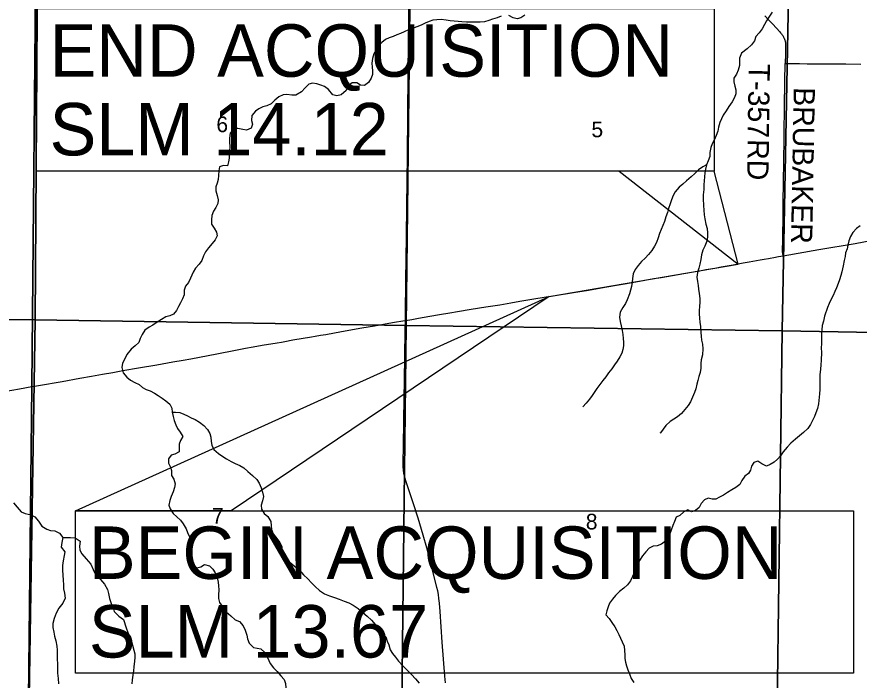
# Model space of a CAD drawing. Extents: x -8.8 to 41.4, y 0 to 34.6.
# Drawn here: x -5.453 to -3.204, y 16.599 to 18.37 of the extents above; entities that cross this region are included whole.
import ezdxf

# ---------------------------------------------------------------- set-up
doc = ezdxf.new("R2010")
doc.units = 0
for name, color, linetype in [('Default', 7, 'Continuous'), ('GM_X_Corporation', 7, 'Continuous'), ('GM_X_County_Road', 7, 'Continuous'), ('GM_X_Minor_River', 7, 'Continuous'), ('GM_X_Section_Text', 7, 'Continuous'), ('GM_X_State_Route', 7, 'Continuous'), ('GM_X_Township_Road', 7, 'Continuous'), ('GM_X_Township_Text', 7, 'Continuous'), ('SH_Border', 7, 'Continuous'), ('SH_Data', 7, 'Continuous')]:
    doc.layers.add(name, color=color, linetype=linetype)

msp = doc.modelspace()

# ---------------------------------------------------------------- linework, layer by layer
at = {"layer": 'GM_X_Corporation'}
for points in [[(-8.6743, 18.6925), (-8.6743, 14.1), (-5.4442, 14.1), (-5.4432, 14.2265), (-5.4429, 14.2618), (-5.4404, 14.5882), (-5.4368, 15.0446), (-5.435, 15.3164), (-5.4282, 16.3507), (-5.4212, 16.5483), (-5.4129, 17.3836), (-5.4008, 18.6369)], [(-5.4008, 18.6369), (-5.4129, 17.3836), (-5.4212, 16.5483), (-5.4282, 16.3507), (-5.435, 15.3164), (-5.4368, 15.0446), (-5.4404, 14.5882), (-5.4429, 14.2618), (-5.4432, 14.2265), (-5.4442, 14.1), (-1.8743, 14.1), (-1.8743, 18.5906)]]:
    msp.add_lwpolyline(points, dxfattribs=at)
for points in [[(-6.4037, 18.6579), (-5.3971, 18.6428), (-5.4036, 17.5614), (-6.4092, 17.5696)], [(-5.3971, 18.6428), (-4.4269, 18.629), (-4.4012, 18.628), (-4.4134, 17.5464), (-5.4036, 17.5614)], [(-4.4012, 18.628), (-3.4272, 18.6145), (-3.3893, 18.614), (-3.4102, 17.5315), (-4.4134, 17.5464)], [(-3.3893, 18.614), (-2.4092, 18.5999), (-2.4162, 17.5144), (-3.4102, 17.5315)], [(-5.4036, 17.5614), (-5.4203, 16.5519), (-6.4339, 16.586), (-6.4092, 17.5696)], [(-4.4134, 17.5464), (-4.4254, 16.539), (-5.4203, 16.5519), (-5.4036, 17.5614)], [(-3.4102, 17.5315), (-3.4233, 16.5283), (-4.4254, 16.539), (-4.4134, 17.5464)], [(-2.4162, 17.5144), (-2.421, 16.5107), (-3.4233, 16.5283), (-3.4102, 17.5315)]]:
    msp.add_lwpolyline(points, close=True, dxfattribs=at)
at = {"layer": 'GM_X_County_Road'}
for points in [[(-4.4156, 17.5596), (-4.4156, 17.5608), (-4.4157, 17.577), (-4.4143, 17.6658), (-4.4129, 17.7838), (-4.4119, 17.8646), (-4.4102, 17.9994), (-4.409, 18.1094), (-4.4082, 18.2175), (-4.4071, 18.3032), (-4.4063, 18.3609), (-4.4057, 18.4379), (-4.4051, 18.51), (-4.4044, 18.5765), (-4.4046, 18.5896), (-4.405, 18.5964), (-4.4057, 18.6014), (-4.4066, 18.6057), (-4.4077, 18.6094), (-4.4095, 18.6141), (-4.4119, 18.6189), (-4.4135, 18.6221), (-4.4151, 18.6247), (-4.4171, 18.6274)], [(-4.3088, 16.5919), (-4.3103, 16.6099), (-4.317, 16.7004), (-4.3228, 16.7822), (-4.3246, 16.8045), (-4.3261, 16.8175), (-4.3276, 16.828), (-4.3293, 16.8372), (-4.3314, 16.8469), (-4.3501, 16.9223), (-4.3581, 16.9528), (-4.3679, 16.9864), (-4.3811, 17.0315), (-4.3939, 17.0701), (-4.4072, 17.1096), (-4.4134, 17.1284), (-4.4169, 17.1403), (-4.4193, 17.1505), (-4.4208, 17.1603), (-4.4215, 17.1689), (-4.4217, 17.1782), (-4.4208, 17.226), (-4.4191, 17.3527), (-4.4183, 17.3993), (-4.4162, 17.531), (-4.4156, 17.5596)]]:
    msp.add_lwpolyline(points, dxfattribs=at)
at = {"layer": 'GM_X_Minor_River'}
for points in [[(-4.1595, 18.372), (-4.1709, 18.368), (-4.1828, 18.3637), (-4.1927, 18.3601), (-4.2042, 18.3572), (-4.2159, 18.3559), (-4.2281, 18.3562), (-4.2402, 18.3556), (-4.2527, 18.3559), (-4.2645, 18.3568), (-4.2747, 18.3578), (-4.2853, 18.3584), (-4.2963, 18.3597), (-4.3069, 18.3614), (-4.3202, 18.3632), (-4.3315, 18.3626), (-4.3422, 18.3613), (-4.3521, 18.3577), (-4.3625, 18.353), (-4.3736, 18.3483), (-4.3846, 18.3439), (-4.3965, 18.3392), (-4.4076, 18.3352), (-4.4187, 18.3301)], [(-4.0968, 18.3746), (-4.1072, 18.3676), (-4.1171, 18.3651), (-4.1281, 18.3676), (-4.1397, 18.3739)], [(-3.4368, 18.3828), (-3.4454, 18.3697), (-3.4517, 18.3599), (-3.4568, 18.3498), (-3.4631, 18.3378), (-3.4716, 18.3277), (-3.4798, 18.318), (-3.4841, 18.3063), (-3.4916, 18.2951), (-3.5028, 18.2847), (-3.5181, 18.2736), (-3.5233, 18.26), (-3.5235, 18.2502), (-3.5241, 18.2399), (-3.5269, 18.2279), (-3.5321, 18.2169), (-3.5391, 18.2065), (-3.5389, 18.197), (-3.5365, 18.1852), (-3.5332, 18.1753), (-3.5338, 18.1647), (-3.5374, 18.1549), (-3.5437, 18.1432), (-3.5523, 18.1309), (-3.5597, 18.1193), (-3.5671, 18.108), (-3.5758, 18.0877), (-3.5795, 18.0756), (-3.5819, 18.0647), (-3.5856, 18.0538), (-3.5907, 18.0429), (-3.597, 18.0312), (-3.6002, 18.021), (-3.6027, 18.0082), (-3.6033, 17.9972), (-3.6077, 17.9859), (-3.612, 17.975), (-3.6149, 17.9637), (-3.6162, 17.9535), (-3.6172, 17.9432), (-3.6181, 17.9323), (-3.6187, 17.9213), (-3.6193, 17.9095), (-3.6204, 17.8948), (-3.6205, 17.8845), (-3.6194, 17.8663), (-3.6188, 17.8542), (-3.6179, 17.8413), (-3.6162, 17.8306), (-3.6134, 17.8165), (-3.6102, 17.8047), (-3.6089, 17.7937), (-3.6092, 17.7816), (-3.6112, 17.771), (-3.6164, 17.7582), (-3.6219, 17.7469), (-3.6248, 17.7348), (-3.6273, 17.7224), (-3.6298, 17.7095), (-3.6319, 17.6993), (-3.6355, 17.688), (-3.6377, 17.6755), (-3.636, 17.6638), (-3.6343, 17.6527), (-3.6333, 17.6432), (-3.6317, 17.6311), (-3.63, 17.6185), (-3.6298, 17.6075), (-3.6304, 17.5977)], [(-4.4187, 18.3301), (-4.429, 18.3254), (-4.4385, 18.3218), (-4.4485, 18.3182), (-4.4592, 18.3142), (-4.4687, 18.3094), (-4.4788, 18.3017), (-4.4873, 18.2916), (-4.4935, 18.2818), (-4.4998, 18.2713), (-4.5034, 18.2589), (-4.5052, 18.2464), (-4.5046, 18.2358), (-4.5037, 18.2259), (-4.5035, 18.216), (-4.5071, 18.2063), (-4.5137, 18.195), (-4.5245, 18.1869), (-4.5351, 18.1882), (-4.5456, 18.1944), (-4.5578, 18.1939), (-4.5674, 18.1865), (-4.5737, 18.1734), (-4.5872, 18.1622), (-4.599, 18.159), (-4.6096, 18.1623), (-4.6207, 18.1765), (-4.6312, 18.1839), (-4.641, 18.1882), (-4.6519, 18.1915), (-4.6633, 18.1932), (-4.6732, 18.1904), (-4.6829, 18.1803), (-4.6929, 18.1699), (-4.7082, 18.1614), (-4.7189, 18.1609), (-4.7317, 18.163), (-4.742, 18.1617), (-4.7531, 18.157), (-4.7639, 18.1481), (-4.7735, 18.1384), (-4.785, 18.1329), (-4.7957, 18.1297), (-4.8064, 18.125), (-4.816, 18.1183), (-4.8257, 18.1071), (-4.8267, 18.0931), (-4.8235, 18.0836), (-4.8275, 18.073), (-4.8393, 18.0679), (-4.8492, 18.0696), (-4.8624, 18.0725), (-4.8723, 18.0719), (-4.8831, 18.0596), (-4.8853, 18.0464), (-4.8851, 18.0362), (-4.8842, 18.0236), (-4.8848, 18.0123), (-4.8859, 17.9933), (-4.888, 17.9835), (-4.8904, 17.9726), (-4.901, 17.9735), (-4.9114, 17.9695), (-4.9138, 17.9593), (-4.9141, 17.9468), (-4.9154, 17.9359), (-4.9182, 17.9261), (-4.9214, 17.9163), (-4.9213, 17.9053), (-4.9177, 17.8934), (-4.9149, 17.882), (-4.9162, 17.8718), (-4.9217, 17.8613), (-4.928, 17.8512), (-4.932, 17.8395), (-4.9333, 17.8281), (-4.9335, 17.8171), (-4.9261, 17.8064), (-4.9195, 17.7957), (-4.9178, 17.7854), (-4.9233, 17.7749), (-4.9311, 17.7652), (-4.9411, 17.7532), (-4.9493, 17.7424), (-4.9548, 17.7318), (-4.9588, 17.7198), (-4.9658, 17.7097), (-4.9755, 17.6992), (-4.9818, 17.6887), (-4.9893, 17.6726), (-4.9944, 17.6609), (-5.0022, 17.6508), (-5.0058, 17.6403), (-5.0064, 17.6278), (-5.0108, 17.6172), (-5.0163, 17.6067), (-5.021, 17.5966), (-5.0266, 17.5861), (-5.0347, 17.5764), (-5.0443, 17.5716), (-5.0549, 17.5688)], [(-3.612, 17.975), (-3.622, 17.9695), (-3.6332, 17.9614), (-3.6432, 17.9521), (-3.6529, 17.9431), (-3.6648, 17.932), (-3.6748, 17.9238), (-3.6845, 17.9153), (-3.6953, 17.9026), (-3.7008, 17.8929), (-3.7048, 17.8819), (-3.7084, 17.871), (-3.7128, 17.8586), (-3.7161, 17.848), (-3.7201, 17.836), (-3.7241, 17.8235), (-3.7372, 17.7919), (-3.7412, 17.7799), (-3.7456, 17.7678), (-3.7507, 17.7577), (-3.7578, 17.7468), (-3.7667, 17.7356), (-3.7756, 17.7259), (-3.7856, 17.717), (-3.7946, 17.7065), (-3.8024, 17.6957), (-3.8071, 17.6844), (-3.8092, 17.6719), (-3.8106, 17.6617), (-3.8123, 17.65), (-3.8144, 17.6402), (-3.8176, 17.6304), (-3.824, 17.6149), (-3.8283, 17.6048), (-3.835, 17.5939), (-3.842, 17.5815), (-3.8442, 17.5687), (-3.8425, 17.5565), (-3.8393, 17.5455), (-3.8369, 17.5325), (-3.8348, 17.5219), (-3.8338, 17.5116), (-3.8333, 17.5014), (-3.833, 17.4919), (-3.8347, 17.482), (-3.8376, 17.4722), (-3.8431, 17.4621), (-3.8501, 17.4512), (-3.8571, 17.4415), (-3.8645, 17.4303), (-3.8731, 17.4198), (-3.8809, 17.4093), (-3.8882, 17.3996), (-3.8964, 17.3888), (-3.9042, 17.3779), (-3.9171, 17.3592), (-3.9245, 17.3491), (-3.933, 17.3387), (-3.9415, 17.329)], [(-3.2014, 17.8123), (-3.2115, 17.8049), (-3.2211, 17.794), (-3.227, 17.7835), (-3.2322, 17.7723), (-3.2346, 17.7609), (-3.2367, 17.7507), (-3.2403, 17.7402), (-3.242, 17.7303), (-3.2441, 17.7194), (-3.2471, 17.705), (-3.2504, 17.6895), (-3.2528, 17.6794), (-3.2565, 17.668), (-3.2604, 17.6579), (-3.2644, 17.647), (-3.2692, 17.6372), (-3.2739, 17.6263), (-3.2787, 17.6161), (-3.2842, 17.6045), (-3.2886, 17.5939), (-3.2966, 17.5713), (-3.2999, 17.5578), (-3.3027, 17.5461), (-3.3041, 17.5343), (-3.3047, 17.5214), (-3.3049, 17.5097), (-3.3047, 17.4983), (-3.3054, 17.4858), (-3.3052, 17.4748), (-3.3056, 17.4528), (-3.3062, 17.4418), (-3.3072, 17.4286), (-3.3089, 17.4154), (-3.3095, 17.4025), (-3.3094, 17.3922), (-3.3093, 17.3748), (-3.3099, 17.3638), (-3.313, 17.3373), (-3.3155, 17.3245), (-3.3199, 17.3132), (-3.3239, 17.303), (-3.3286, 17.2925), (-3.3342, 17.2816), (-3.3416, 17.2707), (-3.3528, 17.26), (-3.3639, 17.2514), (-3.3743, 17.2429), (-3.3863, 17.2321)], [(-3.6304, 17.5977), (-3.6317, 17.5856), (-3.6315, 17.5761), (-3.6306, 17.5662), (-3.6293, 17.5544), (-3.6279, 17.5442), (-3.6267, 17.5275), (-3.6261, 17.518), (-3.6248, 17.5066), (-3.6228, 17.4959), (-3.6215, 17.4841), (-3.6229, 17.4679), (-3.6258, 17.4543), (-3.6267, 17.4444), (-3.627, 17.4323), (-3.6287, 17.4206), (-3.6323, 17.41), (-3.6348, 17.3994), (-3.6376, 17.3893), (-3.6405, 17.3768), (-3.6441, 17.367), (-3.6493, 17.355), (-3.6548, 17.3426), (-3.6611, 17.3321), (-3.6692, 17.322), (-3.6789, 17.3108), (-3.6889, 17.3022), (-3.6993, 17.2956), (-3.7089, 17.2894), (-3.7201, 17.2789), (-3.7279, 17.2692), (-3.7345, 17.2595), (-3.736, 17.2584)], [(-5.0549, 17.5688), (-5.0665, 17.5622), (-5.078, 17.5548), (-5.0899, 17.547), (-5.0998, 17.5419), (-5.111, 17.5338), (-5.118, 17.5218), (-5.1232, 17.5116), (-5.1275, 17.5011), (-5.1372, 17.4922), (-5.1476, 17.4829), (-5.1589, 17.4683), (-5.1648, 17.457), (-5.1703, 17.4454), (-5.1724, 17.4337), (-5.1685, 17.4196), (-5.1592, 17.408), (-5.1491, 17.3999), (-5.1379, 17.3936), (-5.1266, 17.3885), (-5.1169, 17.3803), (-5.1071, 17.3748), (-5.0965, 17.3712), (-5.0856, 17.3657), (-5.0759, 17.3591), (-5.0646, 17.3521), (-5.0549, 17.3451), (-5.0444, 17.3358), (-5.0386, 17.3254), (-5.0384, 17.3148), (-5.0359, 17.303), (-5.0327, 17.2923), (-5.0284, 17.2813), (-5.0236, 17.2713), (-5.0166, 17.2609), (-5.01, 17.2494), (-5.0159, 17.2393), (-5.0198, 17.2292), (-5.0193, 17.2193), (-5.0191, 17.209), (-5.0306, 17.2024), (-5.0409, 17.2), (-5.0483, 17.1902), (-5.0481, 17.1785), (-5.0422, 17.1681), (-5.0401, 17.1586), (-5.0396, 17.1457), (-5.0333, 17.1358), (-5.0298, 17.1236), (-5.0318, 17.1134), (-5.0358, 17.1021), (-5.0406, 17.0896), (-5.0446, 17.0787), (-5.0467, 17.0662), (-5.0431, 17.0567), (-5.0354, 17.0437), (-5.0257, 17.0355), (-5.0156, 17.0266), (-5.0086, 17.0162), (-5.0012, 17.0028), (-4.9969, 16.9933), (-4.9918, 16.9818), (-4.9924, 16.9697), (-4.9971, 16.958), (-4.9989, 16.9471), (-4.9983, 16.9376), (-4.9985, 16.9277), (-4.991, 16.9181), (-4.9836, 16.9085), (-4.972, 16.8992), (-4.9617, 16.902), (-4.9518, 16.9083), (-4.9389, 16.9042), (-4.9292, 16.8953), (-4.923, 16.8854), (-4.9179, 16.8724), (-4.9155, 16.8606), (-4.9145, 16.8511), (-4.9139, 16.8405), (-4.9146, 16.8268), (-4.9147, 16.817), (-4.9115, 16.8067), (-4.903, 16.7936), (-4.8941, 16.7817), (-4.8818, 16.7705), (-4.8703, 16.7604), (-4.8586, 16.7556), (-4.8482, 16.7444), (-4.8431, 16.7326), (-4.8391, 16.7196), (-4.837, 16.7097), (-4.8323, 16.6983), (-4.8211, 16.6867), (-4.8113, 16.6846), (-4.8011, 16.6825), (-4.7907, 16.6729), (-4.7833, 16.6598), (-4.7768, 16.6438), (-4.7675, 16.6319), (-4.7578, 16.6222), (-4.7482, 16.6107)], [(-5.0384, 17.3148), (-5.0289, 17.3146), (-5.0175, 17.314), (-5.0074, 17.3097), (-4.9976, 17.3053), (-4.987, 17.2998), (-4.9769, 17.2947), (-4.9653, 17.2884), (-4.9537, 17.2795), (-4.9436, 17.2683), (-4.9377, 17.2576), (-4.9353, 17.2481), (-4.934, 17.2363), (-4.9326, 17.2264), (-4.9268, 17.2153), (-4.9144, 17.2045), (-4.9028, 17.1967), (-4.8927, 17.1904), (-4.8807, 17.183), (-4.8698, 17.1775), (-4.8574, 17.1723), (-4.8472, 17.1657), (-4.8364, 17.156), (-4.8233, 17.1455), (-4.8125, 17.1351), (-4.8055, 17.1255), (-4.8004, 17.1125), (-4.7968, 17.1007), (-4.794, 17.0896), (-4.7969, 17.0775), (-4.8005, 17.0666), (-4.7995, 17.056), (-4.7926, 17.0441), (-4.7825, 17.0363), (-4.7744, 17.0229), (-4.7738, 17.0111), (-4.7732, 17.0016), (-4.7681, 16.9894), (-4.7585, 16.9771), (-4.7507, 16.9663), (-4.7452, 16.956), (-4.7458, 16.9462), (-4.7464, 16.9344), (-4.7364, 16.9221), (-4.7251, 16.9151), (-4.7117, 16.9031), (-4.699, 16.8933), (-4.6874, 16.8806), (-4.6762, 16.8698), (-4.6658, 16.8594), (-4.6561, 16.8493), (-4.6446, 16.8381), (-4.6315, 16.8292), (-4.6183, 16.824), (-4.6051, 16.8199), (-4.5923, 16.8155), (-4.5787, 16.8104), (-4.5663, 16.8056), (-4.5546, 16.7997), (-4.5415, 16.7903), (-4.5288, 16.7802), (-4.5176, 16.7702), (-4.506, 16.759), (-4.4952, 16.7466), (-4.4863, 16.7366), (-4.4763, 16.725), (-4.4681, 16.7147), (-4.4638, 16.7036), (-4.4598, 16.6933), (-4.4562, 16.6803), (-4.45, 16.67), (-4.4422, 16.6603), (-4.434, 16.6496), (-4.4221, 16.6376), (-4.4102, 16.6249), (-4.3994, 16.6144), (-4.389, 16.6025), (-4.379, 16.5909)], [(-3.3863, 17.2321), (-3.3964, 17.221), (-3.4068, 17.2086), (-3.4146, 17.1985), (-3.422, 17.1888), (-3.4316, 17.181), (-3.4416, 17.1748), (-3.4515, 17.1704), (-3.4643, 17.1771), (-3.4752, 17.1841), (-3.4855, 17.1802), (-3.4914, 17.1704), (-3.4946, 17.1602), (-3.4993, 17.1505), (-3.5093, 17.1442), (-3.5175, 17.1318), (-3.5226, 17.1217), (-3.5334, 17.1139), (-3.5445, 17.1077), (-3.556, 17.1003), (-3.566, 17.0933), (-3.5768, 17.0878), (-3.5867, 17.0827), (-3.597, 17.0825), (-3.6072, 17.0854), (-3.6171, 17.0802), (-3.6257, 17.0705), (-3.6315, 17.0604), (-3.6412, 17.0522), (-3.6522, 17.0483), (-3.662, 17.0538), (-3.672, 17.0486), (-3.6828, 17.0386), (-3.6924, 17.0339), (-3.6971, 17.023), (-3.7015, 17.012), (-3.7063, 17), (-3.7099, 16.9902), (-3.7142, 16.9804), (-3.7212, 16.9699), (-3.7316, 16.9622), (-3.7431, 16.9578), (-3.7545, 16.9565), (-3.7648, 16.9514), (-3.7737, 16.9417), (-3.7827, 16.9309), (-3.7909, 16.9185), (-3.7964, 16.9073), (-3.8095, 16.8757), (-3.815, 16.8644), (-3.8228, 16.8535), (-3.8328, 16.8446), (-3.844, 16.8354), (-3.8548, 16.8249), (-3.8626, 16.8152), (-3.8711, 16.8051), (-3.8743, 16.795), (-3.8776, 16.784), (-3.8808, 16.7739), (-3.8715, 16.7634), (-3.8641, 16.7527), (-3.8567, 16.7412), (-3.8508, 16.7316), (-3.8457, 16.7213), (-3.8414, 16.7109), (-3.8366, 16.7014), (-3.8315, 16.6899), (-3.8306, 16.6785), (-3.83, 16.6667), (-3.8298, 16.6573), (-3.8281, 16.647), (-3.8256, 16.6371), (-3.822, 16.6268), (-3.8177, 16.6157), (-3.8126, 16.6035), (-3.8056, 16.5931)], [(-5.462, 17.0723), (-5.4517, 17.0611), (-5.441, 17.0483), (-5.4305, 17.0442), (-5.4146, 17.0404), (-5.4045, 17.0356), (-5.3946, 17.0236), (-5.3862, 17.0105), (-5.3731, 17.0022), (-5.363, 16.9986), (-5.3512, 16.9979), (-5.3392, 16.9919), (-5.3301, 16.9796), (-5.3323, 16.9667), (-5.3341, 16.9546), (-5.3249, 16.9415), (-5.3263, 16.9317), (-5.3293, 16.9177), (-5.3312, 16.9049), (-5.3307, 16.8924), (-5.3299, 16.8798), (-5.3287, 16.8665), (-5.3283, 16.8532), (-5.3278, 16.843), (-5.3254, 16.8312), (-5.3238, 16.8179), (-5.3302, 16.8047), (-5.3404, 16.7917), (-5.348, 16.7782), (-5.3533, 16.764), (-5.357, 16.75), (-5.3569, 16.7394), (-5.3542, 16.7268), (-5.3522, 16.7165), (-5.3483, 16.7039), (-5.346, 16.6898), (-5.3447, 16.6796), (-5.3447, 16.6667), (-5.3449, 16.6568), (-5.3445, 16.6412), (-5.3445, 16.6299), (-5.344, 16.6181), (-5.3425, 16.6036), (-5.3417, 16.5892)], [(-5.3301, 16.9796), (-5.3225, 16.9798), (-5.3099, 16.9798), (-5.2967, 16.9791), (-5.2833, 16.9705), (-5.2851, 16.9572), (-5.285, 16.9466), (-5.2792, 16.9362), (-5.2674, 16.923), (-5.2552, 16.9091), (-5.2487, 16.8945), (-5.2433, 16.8826), (-5.2293, 16.8675), (-5.2186, 16.8555), (-5.211, 16.8409), (-5.2078, 16.8306), (-5.2051, 16.8172), (-5.2009, 16.8038), (-5.1955, 16.7927), (-5.1931, 16.782), (-5.1809, 16.7696), (-5.1682, 16.7613), (-5.1612, 16.7384), (-5.1566, 16.7265), (-5.1508, 16.7142), (-5.1469, 16.7028), (-5.1442, 16.6921), (-5.1407, 16.6795), (-5.1379, 16.6692), (-5.1374, 16.6593), (-5.1384, 16.6495), (-5.1403, 16.6343), (-5.1417, 16.6238), (-5.1431, 16.6128), (-5.1449, 16.5996), (-5.1456, 16.589)], [(-4.7482, 16.6107), (-4.7389, 16.6006), (-4.7356, 16.5903), (-4.7343, 16.5785), (-4.7364, 16.5676), (-4.7389, 16.5574), (-4.7315, 16.5459), (-4.7203, 16.5392), (-4.709, 16.5345), (-4.6992, 16.5313), (-4.6906, 16.5205), (-4.6909, 16.5084), (-4.6914, 16.4981), (-4.6916, 16.4883), (-4.6926, 16.4781)]]:
    msp.add_lwpolyline(points, dxfattribs=at)
at = {"layer": 'GM_X_State_Route'}
for points in [[(-5.4117, 17.3832), (-5.3947, 17.3863), (-5.3322, 17.397), (-5.2844, 17.4052), (-5.2538, 17.4106), (-5.2245, 17.4158), (-5.1969, 17.4206), (-5.17, 17.4255), (-5.1278, 17.4327), (-5.0795, 17.4413), (-5.0366, 17.4491), (-5.0085, 17.4539), (-4.9883, 17.4575), (-4.9419, 17.4664), (-4.9187, 17.4707), (-4.8687, 17.4803), (-4.8424, 17.4854), (-4.8217, 17.4892), (-4.7978, 17.4932), (-4.7579, 17.5), (-4.7463, 17.502), (-4.7378, 17.5036), (-4.7163, 17.5074), (-4.6661, 17.5159), (-4.6563, 17.5176), (-4.6422, 17.52), (-4.6282, 17.5224), (-4.586, 17.53), (-4.5321, 17.5396), (-4.4978, 17.5456), (-4.4501, 17.5539), (-4.417, 17.5594), (-4.4156, 17.5596), (-4.398, 17.5624), (-4.3808, 17.5653), (-4.3502, 17.5707), (-4.3245, 17.5751), (-4.2969, 17.5798), (-4.2761, 17.5831), (-4.2399, 17.5893), (-4.2007, 17.5957), (-4.1639, 17.6017), (-4.1339, 17.6066), (-4.11, 17.6108), (-4.0781, 17.616), (-4.0401, 17.6223), (-4.0156, 17.6264), (-3.9665, 17.6342), (-3.9266, 17.6407), (-3.8776, 17.6491), (-3.8519, 17.6535), (-3.8311, 17.6572), (-3.8006, 17.6628), (-3.7528, 17.6713), (-3.7332, 17.6747), (-3.7179, 17.6773), (-3.672, 17.6851), (-3.6463, 17.6895), (-3.6298, 17.6924), (-3.6139, 17.6952), (-3.5894, 17.6994), (-3.5722, 17.7024), (-3.541, 17.708), (-3.5319, 17.7097), (-3.5136, 17.7131), (-3.4977, 17.7161), (-3.4683, 17.7213), (-3.4579, 17.7231), (-3.4463, 17.7253), (-3.4421, 17.7262), (-3.4317, 17.728), (-3.42, 17.7301), (-3.4074, 17.7324), (-3.3118, 17.7487), (-3.2151, 17.7654), (-3.1735, 17.7729)], [(-5.4865, 17.3703), (-5.4461, 17.3772), (-5.4127, 17.3831), (-5.4117, 17.3832)]]:
    msp.add_lwpolyline(points, dxfattribs=at)
at = {"layer": 'GM_X_Township_Road'}
for points in [[(-3.4565, 18.3726), (-3.445, 18.3612), (-3.4399, 18.3559), (-3.4348, 18.3505), (-3.4163, 18.3304), (-3.4143, 18.328), (-3.4119, 18.3252), (-3.4103, 18.3231), (-3.4092, 18.3215), (-3.4083, 18.32), (-3.4072, 18.3183), (-3.406, 18.3163), (-3.4052, 18.3146), (-3.4045, 18.313), (-3.4035, 18.3106), (-3.4026, 18.3081), (-3.4021, 18.3058), (-3.4017, 18.3038), (-3.4013, 18.3019), (-3.4011, 18.3004), (-3.4009, 18.2984), (-3.4008, 18.2949), (-3.4009, 18.2891), (-3.4011, 18.2736), (-3.4013, 18.2656), (-3.4016, 18.2524), (-3.4017, 18.2454)], [(-3.4074, 17.7324), (-3.4083, 17.7376), (-3.4084, 17.7391), (-3.4085, 17.7415), (-3.4085, 17.7447), (-3.4085, 17.7535), (-3.4084, 17.7665), (-3.4081, 17.7826), (-3.4077, 17.8031), (-3.4074, 17.8179), (-3.4072, 17.8408), (-3.407, 17.8577), (-3.4067, 17.88), (-3.4062, 17.9235), (-3.4059, 17.9493), (-3.4057, 17.9631), (-3.4055, 17.9787), (-3.4052, 18.0014), (-3.4049, 18.0282), (-3.4046, 18.046), (-3.4043, 18.0703), (-3.4041, 18.0891), (-3.404, 18.0999), (-3.4039, 18.1118), (-3.4035, 18.1346), (-3.4032, 18.1562), (-3.403, 18.1705), (-3.4026, 18.2041), (-3.4023, 18.2173), (-3.4021, 18.2266), (-3.4018, 18.2334), (-3.4017, 18.2454)], [(-3.4017, 18.2454), (-3.3949, 18.2454), (-3.3844, 18.2454), (-3.3633, 18.2453), (-3.3427, 18.2452), (-3.32, 18.2451), (-3.2959, 18.245), (-3.2713, 18.2448), (-3.2402, 18.2446), (-3.1998, 18.2443)]]:
    msp.add_lwpolyline(points, dxfattribs=at)
at = {"layer": 'SH_Border'}
msp.add_line((-4.0317, 17.6231), (-3.5271, 17.7103), dxfattribs=at)
at = {"layer": 'SH_Data'}
for points in [[(-5.4009, 18.3923), (-3.5915, 18.3923), (-3.5915, 17.9584), (-5.4009, 17.9584)], [(-3.8448, 17.9586), (-3.5271, 17.7103), (-3.5915, 17.9584)], [(-5.2961, 17.0515), (-4.0317, 17.6231), (-4.8804, 17.0512)], [(-5.2961, 17.0515), (-3.2195, 17.0515), (-3.2195, 16.6176), (-5.2961, 16.6176)]]:
    msp.add_lwpolyline(points, close=True, dxfattribs=at)

# ---------------------------------------------------------------- texts
at = {"layer": 'Default'}
for s, p in [('END ACQUISITION', (-5.3654, 18.2103)), ('SLM 14.12', (-5.3654, 18.0003)), ('BEGIN ACQUISITION', (-5.2605, 16.8695)), ('SLM 13.67', (-5.2605, 16.6595))]:
    msp.add_text(s, height=0.14, dxfattribs=at).set_placement(p)
at = {"layer": 'GM_X_Section_Text'}
for s, rotation, p in [('T-357', 269.1574, (-3.4991, 18.2454)), ('BRUBAKER', 268.9905, (-3.379, 18.1827)), ('RD', 269.0118, (-3.5015, 18.044))]:
    msp.add_text(s, height=0.05682, rotation=rotation, dxfattribs=at).set_placement(p)
at = {"layer": 'GM_X_Township_Text'}
for s, p in [('6', (-4.9201, 18.0623)), ('5', (-3.9189, 18.0487)), ('7', (-4.9318, 17.017)), ('8', (-3.9339, 17.0015))]:
    msp.add_text(s, height=0.0419, rotation=0, dxfattribs=at).set_placement(p)

doc.saveas('drawing.dxf')
